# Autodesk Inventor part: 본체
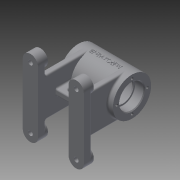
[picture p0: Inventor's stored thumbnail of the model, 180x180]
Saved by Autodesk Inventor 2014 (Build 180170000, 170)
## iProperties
Created: 2015-11
Part Number: 본체
Material: 일반
Document SubType Name: Modeling
Designer: Owner
Density: 1 g/cm^3
Appearance: 기본값
Author: Owner
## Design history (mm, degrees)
sketch "스케치1"
  geometry: L1 (-40, 50)-(-20, 50); L2 (-20, 50)-(-20, -50); L3 (-20, -50)-(-40, -50); L4 (-40, -50)-(-40, 50); L5 (40, 50)-(20, 50); L6 (20, 50)-(20, -50); L7 (20, -50)-(40, -50); L8 (40, -50)-(40, 50); 3 further points
  constraints: 16 end point, 2 parallel, 1 horizontal, 1 horizontal alignment, 1 midpoint, 1 perpendicular
  dimensions: "d0" = 100 distance of L1.end L2.end; "d1" = 20 distance of L1.start L1.end
extrude "돌출1" new body sketch "스케치1" distance "d3" = 10; taper "d4" = 0 deg
sketch "스케치2"
  geometry: L1 (68, 39.159)-(68, -46.601); L2 (0, -50)-(0, 50) reference; L3 (0, 0)-(77.376, 0); C1 r 25 at (68, 0)
  constraints: 4 end point, 2 point on line, 1 centre point, 1 perpendicular, 1 vertical
  dimensions: "d5" = 68 distance between parallel lines of L2 L1; "d6" = 50 diameter of C1
extrude "돌출2" join sketch "스케치2" stored distance "d7" = 70; taper "d8" = 0 deg
sketch "스케치3"
  geometry: C1 r 25 at (0, 0) reference; C2 r 16 at (0, 0); 1 further point
  constraints: 1 centre point, 1 coincident
  dimensions: "d9" = 32 diameter of C2
extrude "돌출3" cut sketch "스케치3" distance "d10" = 12; taper "d11" = 0 deg
sketch "스케치4"
  geometry: C1 r 16 at (0, 0) reference; 1 further point
sketch "스케치5"
  geometry: C1 r 25 at (0, 0) reference; C2 r 16 at (0, 0); 1 further point
  constraints: 1 centre point, 1 coincident
  dimensions: "d12" = 32 diameter of C2
extrude "돌출4" cut sketch "스케치5" distance "d13" = 12; taper "d14" = 0 deg
sketch "스케치6"
  geometry: C1 r 25 at (68, 0) reference; C2 r 21 at (68, 0); 1 further point
  constraints: 1 centre point, 1 coincident
  dimensions: "d15" = 42 diameter of C2
extrude "돌출5" cut sketch "스케치6" stored distance "d16" = 42; taper "d17" = 0 deg
sketch "스케치7"
  geometry: C1 r 16 at (0, 0) reference; C2 r 14 at (0, 0); 1 further point
  constraints: 1 centre point, 1 coincident
  dimensions: "d18" = 28 diameter of C2
extrude "돌출6" cut sketch "스케치7" distance "d19" = 100; taper "d20" = 0 deg
sketch "스케치9"
  geometry: L1 (-40, -50)-(-20, -50) reference; L2 (-20, -50)-(-20, 50) reference; L3 (-20, 50)-(-40, 50) reference; L4 (-40, 50)-(-40, -50) reference; 1 further point
sketch "스케치10"
  geometry: L1 (-20, -50)-(-20, 50) reference; L2 (-28, 25)-(-20, 25); L3 (-20, 25)-(-20, -25); L4 (-20, -25)-(-28, -25); L5 (-28, -25)-(-28, 25); L6 (0, 1.334)-(0, 18.077); L7 (28, 25)-(20, 25); L8 (20, 25)-(20, -25); L9 (20, -25)-(28, -25); L10 (28, -25)-(28, 25); 3 further points
  constraints: 18 end point, 5 symmetric about line, 3 parallel, 1 horizontal, 1 horizontal alignment, 1 midpoint, 1 perpendicular, 1 point on line
  dimensions: "d23" = 50 distance of L4.end L2.start; "d24" = 8 distance of L2.start L2.end
extrude "돌출7" join sketch "스케치10" stored distance "d25" = 10; taper "d26" = 0 deg
node "작업 평면2"
  node "작업 평면1"
sketch "스케치11"
  geometry: L1 (-22.5, 4)-(22.5, 4); L2 (22.5, 4)-(22.5, -4); L3 (22.5, -4)-(-22.5, -4); L4 (-22.5, -4)-(-22.5, 4); 3 further points
  constraints: 8 end point, 2 midpoint, 2 parallel, 1 horizontal, 1 horizontal alignment, 1 perpendicular, 1 vertical alignment
  dimensions: "d28" = 8 distance of L1.end L2.end; "d29" = 45 distance of L1.start L1.end
extrude "돌출8" join sketch "스케치11" stored distance "d30" = 10; taper "d31" = 0 deg
sketch "스케치12"
  geometry: L1 (40, -23)-(60, -23) reference; L2 (20, -13)-(20, -6.454); L3 (28, 6.5)-(12, 6.5); L4 (28, 13.5)-(12, 13.5); A1 r 3.5 centre (28, 10) between (28, 6.5) and (28, 13.5); A2 r 3.5 centre (12, 10) between (12, 13.5) and (12, 6.5); 1 further point
  constraints: 6 end point, 4 point on circle, 2 centre point, 2 tangent, 1 symmetric about line, 1 other
  dimensions: "d34" = 7 diameter of A1
extrude "돌출9" cut sketch "스케치12" distance "d35" = 50; taper "d36" = 0 deg
node "작업 평면4"
  node "작업 평면3"
sketch "스케치13"
  geometry: C1 r 5 at (0, 0); 1 further point
  constraints: 1 centre point, 1 coincident
  dimensions: "d38" = 10 diameter of C1
extrude "돌출10" join sketch "스케치13" stored distance "d39" = 50; taper "d40" = 0 deg
sketch "스케치14"
  geometry: L1 (68, 0)-(43.751, -14); L2 (68, 0)-(96, 0); C1 r 25 at (68, 0) reference; 1 further point
  constraints: 4 end point, 1 equal length, 1 horizontal
  dimensions: "d41" = 28 distance of L1.start L1.end; "d42" = 150 deg angle of L1 L2
node "작업 평면5"
sketch "스케치15"
  geometry: C1 r 6 at (0, 0); 1 further point
  constraints: 1 centre point
  dimensions: "d43" = 12 diameter of C1
extrude "돌출11" join sketch "스케치15" stored distance "d44" = 50; taper "d45" = 0 deg
sketch "스케치16"
  geometry: L1 (-20, 50)-(-40, 50) reference; L2 (-40, -50)-(-20, -50) reference; L3 (40, 50)-(20, 50) reference; L4 (20, -50)-(40, -50) reference; C1 r 10 at (-30, -40); C2 r 10 at (-30, 40); C3 r 10 at (30, 40); C4 r 10 at (30, -40); 5 further points
  constraints: 4 centre point, 4 midpoint, 4 vertical alignment
  dimensions: "d46" = 20 diameter of C1; "d47" = 10 distance of C1.centre point (-30, -50); "d48" = 20 diameter of C2; "d49" = 10 distance from line of L1 C2.centre; "d50" = 20 diameter of C3; "d51" = 10 distance from line of L3 C3.centre; "d52" = 20 diameter of C4; "d53" = 10 distance from line of L4 C4.centre
extrude "돌출12" join sketch "스케치16" distance "d54" = 3; taper "d55" = 0 deg
sketch "스케치17"
  geometry: C1 r 5 at (0, 0) reference; 1 further point
  constraints: 1 coincident
hole "구멍1" sketch "스케치17" at (0, 0) diameter "d56" = 5.188; stored, may be unused: countersink angle "d60" = 90 deg, drill point angle "d62" = 118 deg; dims "d57" = 20, "d58" = 4, "d59" = 2, "d61" = 20
sketch "스케치18"
  geometry: C1 r 6 at (0, 0) reference; 2 further points
  constraints: 1 coincident
hole "구멍2" sketch "스케치18" at (0, 0) diameter "d63" = 5.188; stored, may be unused: countersink angle "d67" = 90 deg, drill point angle "d69" = 118 deg; dims "d64" = 20, "d65" = 4, "d66" = 2, "d68" = 20
sketch "스케치19"
  geometry: L1 (-30, 40)-(-16.576, 40); L2 (-30, 43.111)-(-30, 78.702); C1 r 10 at (0, 0) reference; C2 r 6 at (0, 0); C3 r 6 at (0, 80); C4 r 6 at (-60, 80); C5 r 6 at (-60, 0)
  constraints: 4 centre point, 4 end point, 3 symmetric about line, 1 coincident, 1 horizontal, 1 perpendicular, 3 other
  dimensions: "d70" = 12 diameter of C2
extrude "돌출13" cut sketch "스케치19" distance "d71" = 4; taper "d72" = 0 deg
sketch "스케치20"
  geometry: L1 (-30, 40)-(-22.961, 40); L2 (-30, 42.79)-(-30, 79.412); C1 r 6 at (0, 0) reference; C2 r 3 at (0, 0); C3 r 3 at (0, 80); C4 r 3 at (-60, 80); C5 r 3 at (-60, 0)
  constraints: 4 centre point, 4 end point, 3 symmetric about line, 1 coincident, 1 horizontal, 1 perpendicular, 3 other
  dimensions: "d73" = 6 diameter of C2
extrude "돌출14" cut sketch "스케치20" distance "d74" = 20; taper "d75" = 0 deg
node "작업 평면6"
sketch "스케치21"
  geometry: L1 (-20.606, 3.48)-(20.606, 3.48); L2 (20.606, 3.48)-(20.606, -3.48); L3 (20.606, -3.48)-(-20.606, -3.48); L4 (-20.606, -3.48)-(-20.606, 3.48); L5 (-20.606, 0)-(20.606, 0); L6 (-35, 25)-(35, 25) reference; L7 (0, 3.48)-(0, -3.48); L8 (-35, 25)-(-35, -25) reference; 1 further point
  constraints: 4 end point, 4 midpoint, 2 other
  dimensions: "d76" = 25 distance between parallel lines of L6 L5; "d77" = 35 distance between parallel lines of L8 L7
feature "엠보싱1" sketch "스케치21" dims "d78" = 0.5, "d79" = 0
chamfer "모따기1" distance "d81" = 1; stored, may be unused: second distance "d82" = 2, angle "d83" = 45 deg
sketch "스케치22"
  geometry: C1 r 17 at (0, 0) reference; A1 r 20 centre (0, 0) between (0, 20) and (20, 0); 3 further points
  constraints: 4 point on circle, 1 centre point, 1 coincident
  dimensions: "d84" = 40 diameter of A1
hole "구멍3" sketch "스케치22" at (0, 20), (20, 0), (0, -20), (-20, 0) diameter "d85" = 3.242; stored, may be unused: countersink angle "d89" = 90 deg, drill point angle "d91" = 118 deg; dims "d86" = 8, "d87" = 4, "d88" = 2, "d90" = 10
sketch "스케치23"
  geometry: C1 r 17 at (0, 0) reference; A1 r 20 centre (0, 0) between (0, 20) and (20, 0); 3 further points
  constraints: 4 point on circle, 1 centre point, 1 coincident
  dimensions: "d92" = 40 diameter of A1
hole "구멍4" sketch "스케치23" at (0, 20), (20, 0), (0, -20), (-20, 0) diameter "d93" = 3.242; stored, may be unused: countersink angle "d97" = 90 deg, drill point angle "d99" = 118 deg; dims "d94" = 8, "d95" = 4, "d96" = 2, "d98" = 10
fillet "모깎기2" dims "d100" = 10, "d101" = 3, "d102" = 0.3
fillet "모깎기3" dims "d103" = 2
fillet "모깎기4" dims "d104" = 0.3
node "솔리드1"
other parameters: "d37" = 3
